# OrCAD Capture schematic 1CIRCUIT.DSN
size A
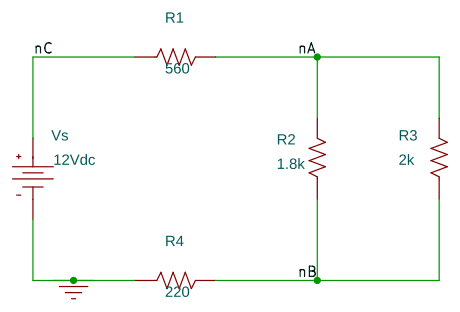
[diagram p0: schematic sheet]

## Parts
R1  560  [AXRC05]
R2  1.8k  [AXRC05]
R3  2k  [AXRC05]
R4  220  [AXRC05]
Vs  VDC

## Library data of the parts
R1-R4 = R
Vs = VDC: DC: 12Vdc

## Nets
0: R4.1 Vs.1(-)
nA: R1.2 R2.2 R3.2
nB: R2.1 R3.1 R4.2
nC: R1.1 Vs.0(+)
